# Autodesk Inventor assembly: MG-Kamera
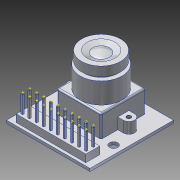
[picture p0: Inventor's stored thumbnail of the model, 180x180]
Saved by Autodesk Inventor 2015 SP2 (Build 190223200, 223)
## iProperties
Created: 2012-10
Part Number: MG-Kamera
Document SubType Name: Assembly
Designer: rYan
Mass: 14.7186 g
Surface Area: 47.0108 cm^2
Volume: 5.43122 cm^3
Density: 2.71 g/cm^3
Author: rYan
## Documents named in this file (3)
- D:\Tigers SVN\mechanik\2016\Inventor\Elektronik\MG-Kamera.iam
- D:\Tigers SVN\mechanik\2016\Inventor\Elektronik\Kamera OV7725.ipt
- D:\Tigers SVN\mechanik\2016\Inventor\Elektronik\Objektiv.ipt
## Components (2 placed, 2 different names)
1. Kamera OV7725:1 — Passend:1, Passend:2
2. Objektiv:1 — Passend:1, Passend:2
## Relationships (2: Mate 2)
- Passend:1 [Mate]: Kamera OV7725:1 ↔ Objektiv:1
- Passend:2 [Mate]: Kamera OV7725:1 ↔ Objektiv:1
